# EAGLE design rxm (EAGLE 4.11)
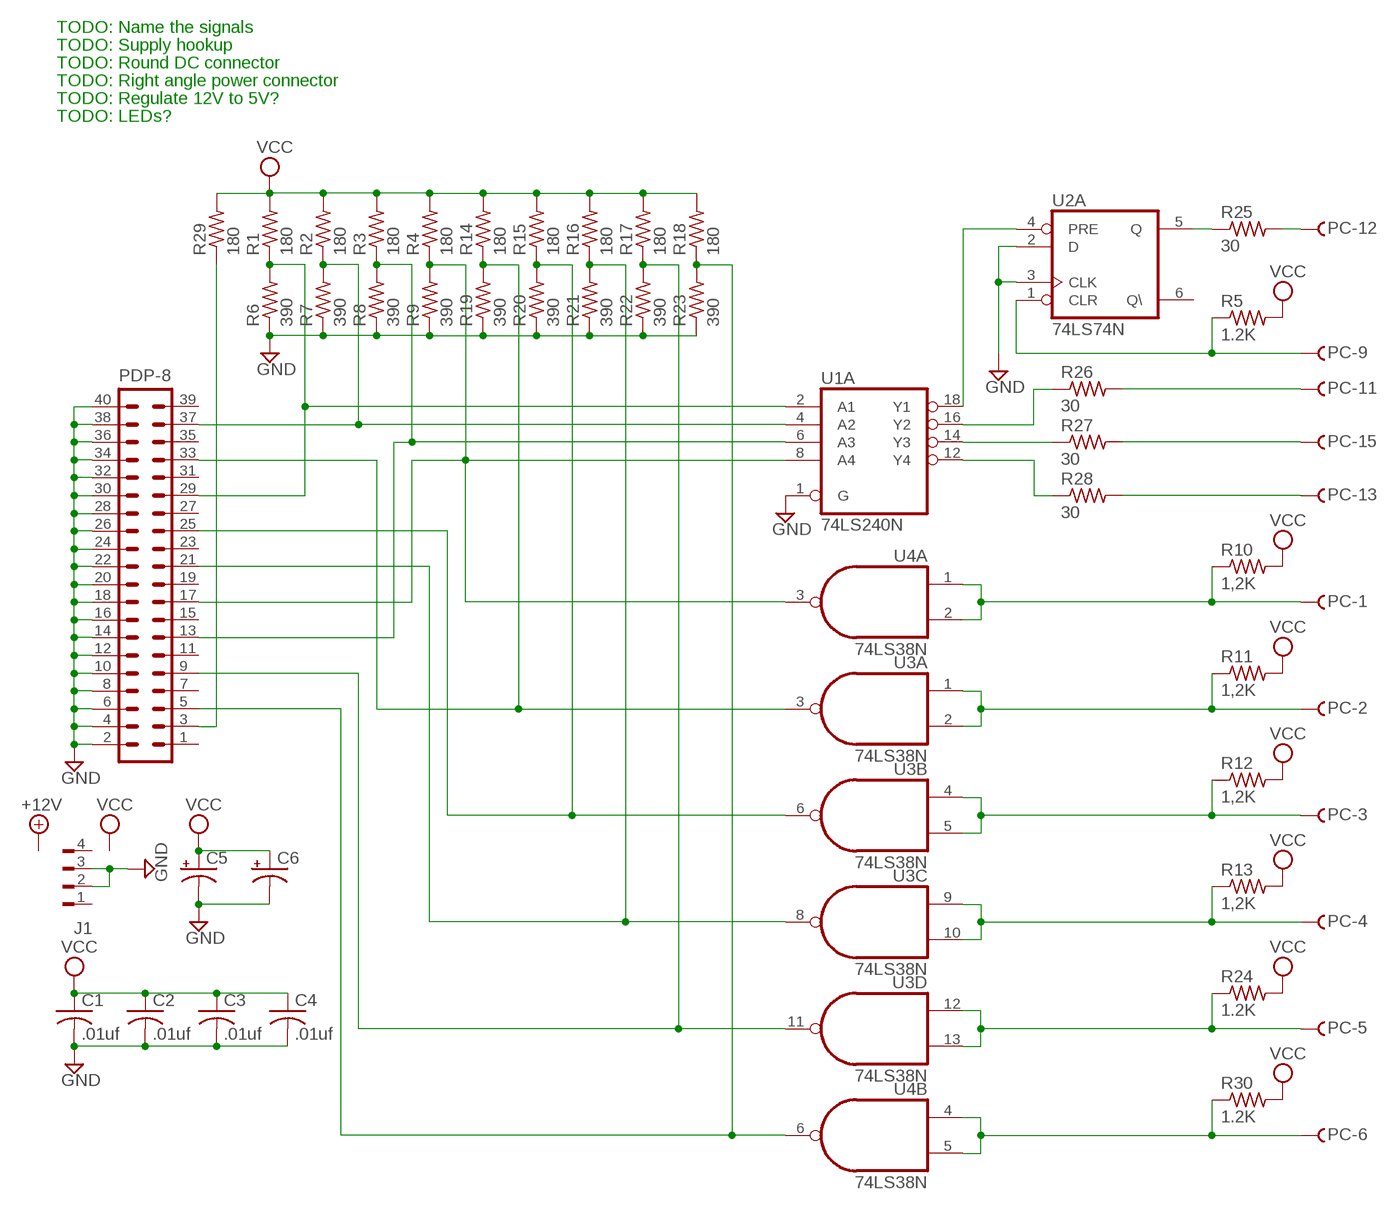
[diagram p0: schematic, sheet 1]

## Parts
C1  .01uf  C-US050-025X075  [C050-025X075]
C2  .01uf  C-US050-025X075  [C050-025X075]
C3  .01uf  C-US050-025X075  [C050-025X075]
C4  .01uf  C-US050-025X075  [C050-025X075]
C5  CPOL-USE2,5-6E  [E2,5-6E]
C6  CPOL-USE2,5-6E  [E2,5-6E]
J1  FLOPPY-4  [FLOPPY-4]
PC  F25HS  [F25H]
PDP-8  40H  [40H]
R1  180  R-US_0207/10  [0207/10]
R2  180  R-US_0207/10  [0207/10]
R3  180  R-US_0207/10  [0207/10]
R4  180  R-US_0207/10  [0207/10]
R5  1.2K  R-US_0207/10  [0207/10]
R6  390  R-US_0207/10  [0207/10]
R7  390  R-US_0207/10  [0207/10]
R8  390  R-US_0207/10  [0207/10]
R9  390  R-US_0207/10  [0207/10]
R10  1,2K  R-US_0207/10  [0207/10]
R11  1,2K  R-US_0207/10  [0207/10]
R12  1,2K  R-US_0207/10  [0207/10]
R13  1,2K  R-US_0207/10  [0207/10]
R14  180  R-US_0207/10  [0207/10]
R15  180  R-US_0207/10  [0207/10]
R16  180  R-US_0207/10  [0207/10]
R17  180  R-US_0207/10  [0207/10]
R18  180  R-US_0207/10  [0207/10]
R19  390  R-US_0207/10  [0207/10]
R20  390  R-US_0207/10  [0207/10]
R21  390  R-US_0207/10  [0207/10]
R22  390  R-US_0207/10  [0207/10]
R23  390  R-US_0207/10  [0207/10]
R24  1.2K  R-US_0207/10  [0207/10]
R25  30  R-US_0207/10  [0207/10]
R26  30  R-US_0207/10  [0207/10]
R27  30  R-US_0207/10  [0207/10]
R28  30  R-US_0207/10  [0207/10]
R29  180  R-US_0207/10  [0207/10]
R30  1.2K  R-US_0207/10  [0207/10]
U1  74LS240N  [DIL20]
U2  74LS74N  [DIL14]
U3  74LS38N  [DIL14]
U4  74LS38N  [DIL14]

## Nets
GND: C1.2 C2.2 C3.2 C4.2 C5.- C6.- J1.2 J1.3 PDP-8.2 PDP-8.4 PDP-8.6 PDP-8.8 PDP-8.10 PDP-8.12 PDP-8.14 PDP-8.16 PDP-8.18 PDP-8.20 PDP-8.22 PDP-8.24 PDP-8.26 PDP-8.28 PDP-8.30 PDP-8.32 PDP-8.34 PDP-8.36 PDP-8.38 PDP-8.40 R6.1 R7.1 R8.1 R9.1 R19.1 R20.1 R21.1 R22.1 R23.1 U1.1(A:G) U2.2(A:D) U2.3(A:CLK)
N$1: PDP-8.29 R1.1 R6.2 U1.2(A:A1)
N$2: PDP-8.37 R2.1 R7.2 U1.4(A:A2)
N$3: PDP-8.13 R3.1 R8.2 U1.6(A:A3)
N$4: PDP-8.17 R4.1 R9.2 U1.8(A:A4) U4.3(A:O)
N$6: PDP-8.33 R14.1 R19.2 U3.3(A:O)
N$7: PDP-8.25 R15.1 R20.2 U3.6(B:O)
N$8: PDP-8.21 R16.1 R21.2 U3.8(C:O)
N$9: PDP-8.9 R17.1 R22.2 U3.11(D:O)
N$10: PDP-8.5 R18.1 R23.2 U4.6(B:O)
N$11: PC.12 R25.2
N$12: PC.11 R26.2
N$13: PC.15 R27.2
N$14: PC.13 R28.2
N$15: PDP-8.3 R29.1
N$16: PC.1 R10.1 U4.1(A:I0) U4.2(A:I1)
N$17: PC.2 R11.1 U3.1(A:I0) U3.2(A:I1)
N$18: PC.3 R12.1 U3.4(B:I0) U3.5(B:I1)
N$19: PC.4 R13.1 U3.9(C:I0) U3.10(C:I1)
N$20: PC.6 R30.1 U4.4(B:I0) U4.5(B:I1)
N$21: PC.5 R24.1 U3.12(D:I0) U3.13(D:I1)
N$22: U1.18(A:Y1) U2.4(A:PRE)
N$23: PC.9 R5.1 U2.1(A:CLR)
N$24: R25.1 U2.5(A:Q)
N$25: R28.1 U1.12(A:Y4)
N$26: R27.1 U1.14(A:Y3)
N$27: R26.1 U1.16(A:Y2)
VCC: C1.1 C2.1 C3.1 C4.1 C5.+ C6.+ R1.2 R2.2 R3.2 R4.2 R5.2 R10.2 R11.2 R12.2 R13.2 R14.2 R15.2 R16.2 R17.2 R18.2 R24.2 R29.2 R30.2
Unconnected: J1.1 J1.4 PC.7 PC.8 PC.10 PC.14 PC.16 PC.17 PC.18 PC.19 PC.20 PC.21 PC.22 PC.23 PC.24 PC.25 PDP-8.1 PDP-8.7 PDP-8.11 PDP-8.15 PDP-8.19 PDP-8.23 PDP-8.27 PDP-8.31 PDP-8.35 PDP-8.39 U1.3(B:Y4) U1.5(B:Y3) U1.7(B:Y2) U1.9(B:Y1) U1.11(B:A1) U1.13(B:A2) U1.15(B:A3) U1.17(B:A4) U1.19(B:G) U2.6(A:Q\) U2.8(B:Q\) U2.9(B:Q) U2.10(B:PRE) U2.11(B:CLK) U2.12(B:D) U2.13(B:CLR) U4.8(C:O) U4.9(C:I0) U4.10(C:I1) U4.11(D:O) U4.12(D:I0) U4.13(D:I1)

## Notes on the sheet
- TODO: Name the signals
- TODO: Supply hookup
- TODO: Round DC connector
- TODO: Right angle power connector
- TODO: Regulate 12V to 5V?
- TODO: LEDs?

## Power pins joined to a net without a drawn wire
GND: U1.10(P:GND) U2.7(P:GND) U3.7(P:GND) U4.7(P:GND)
VCC: U1.20(P:VCC) U2.14(P:VCC) U3.14(P:VCC) U4.14(P:VCC)

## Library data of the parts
C1-C4 = rcl:C-US: CAPACITOR, American symbol
C5 C6 = rcl:CPOL-US: POLARIZED CAPACITOR, American symbol
J1 = con-amp:FLOPPY-4: MATE N-LOCK
PC = con-subd:F25?S: SUB-D
PDP-8 = con-harting-h:40H: CONNECTOR
R1-R30 = rcl:R-US_: RESISTOR, American symbol
U1 = 74xx-jameco:74*240: Octal BUFFER and LINE DRIVER, 3-state
U2 = 74xx-jameco:74*74: Dual D type positive edge triggered FLIP FLOP, preset and clear
U3 U4 = 74xx-jameco:74*38: Quad 2-input NAND gate, open collector output

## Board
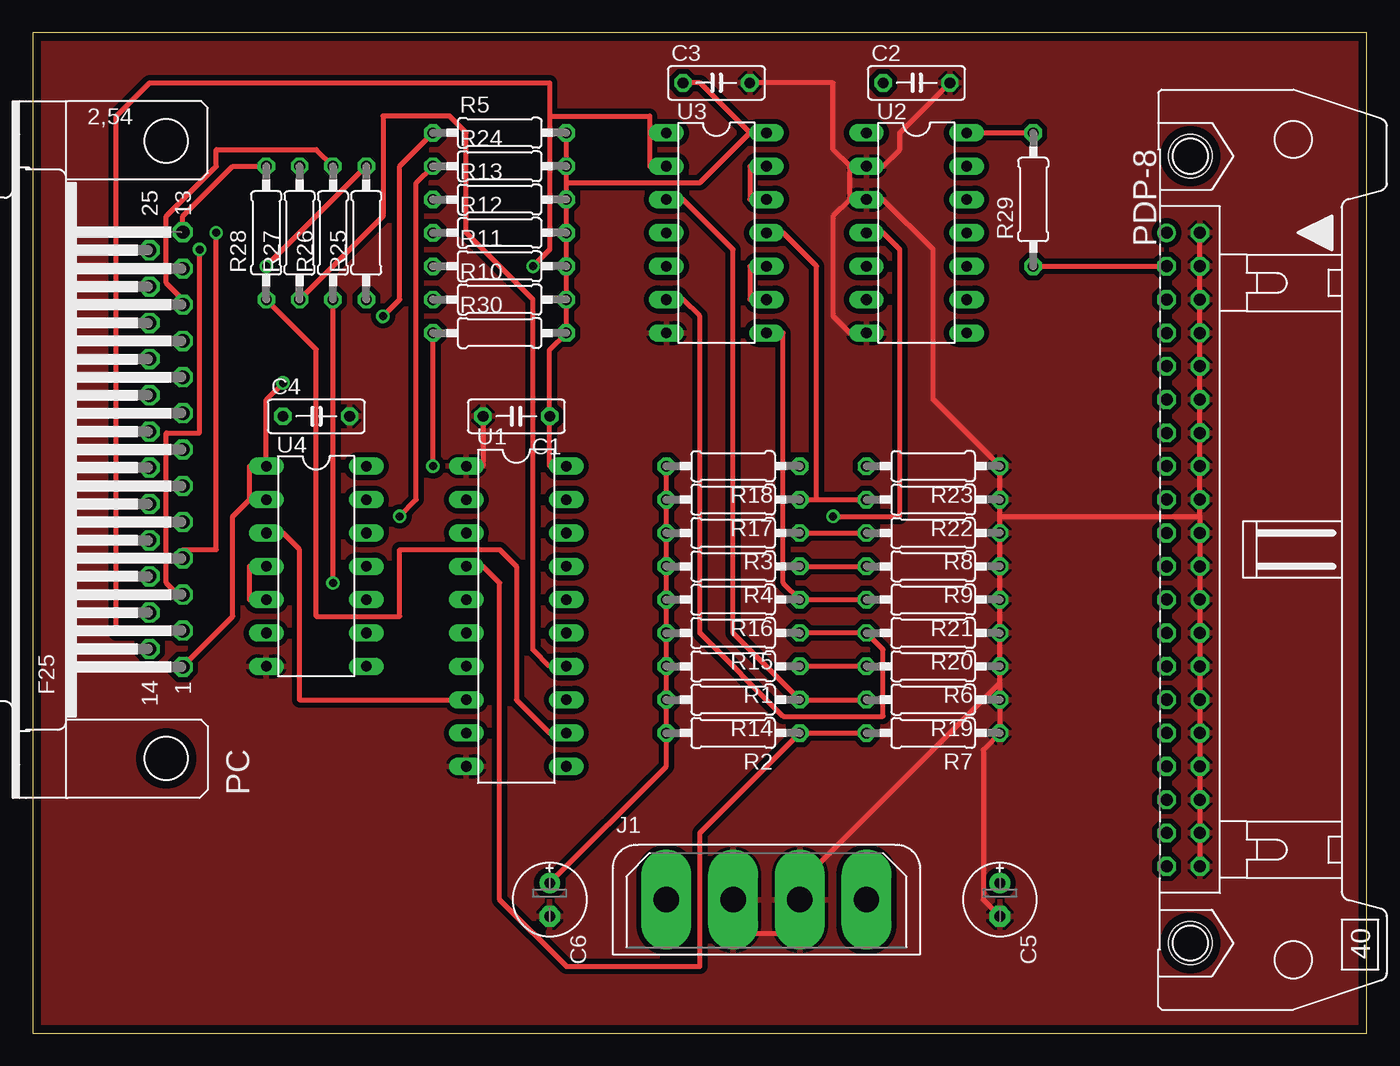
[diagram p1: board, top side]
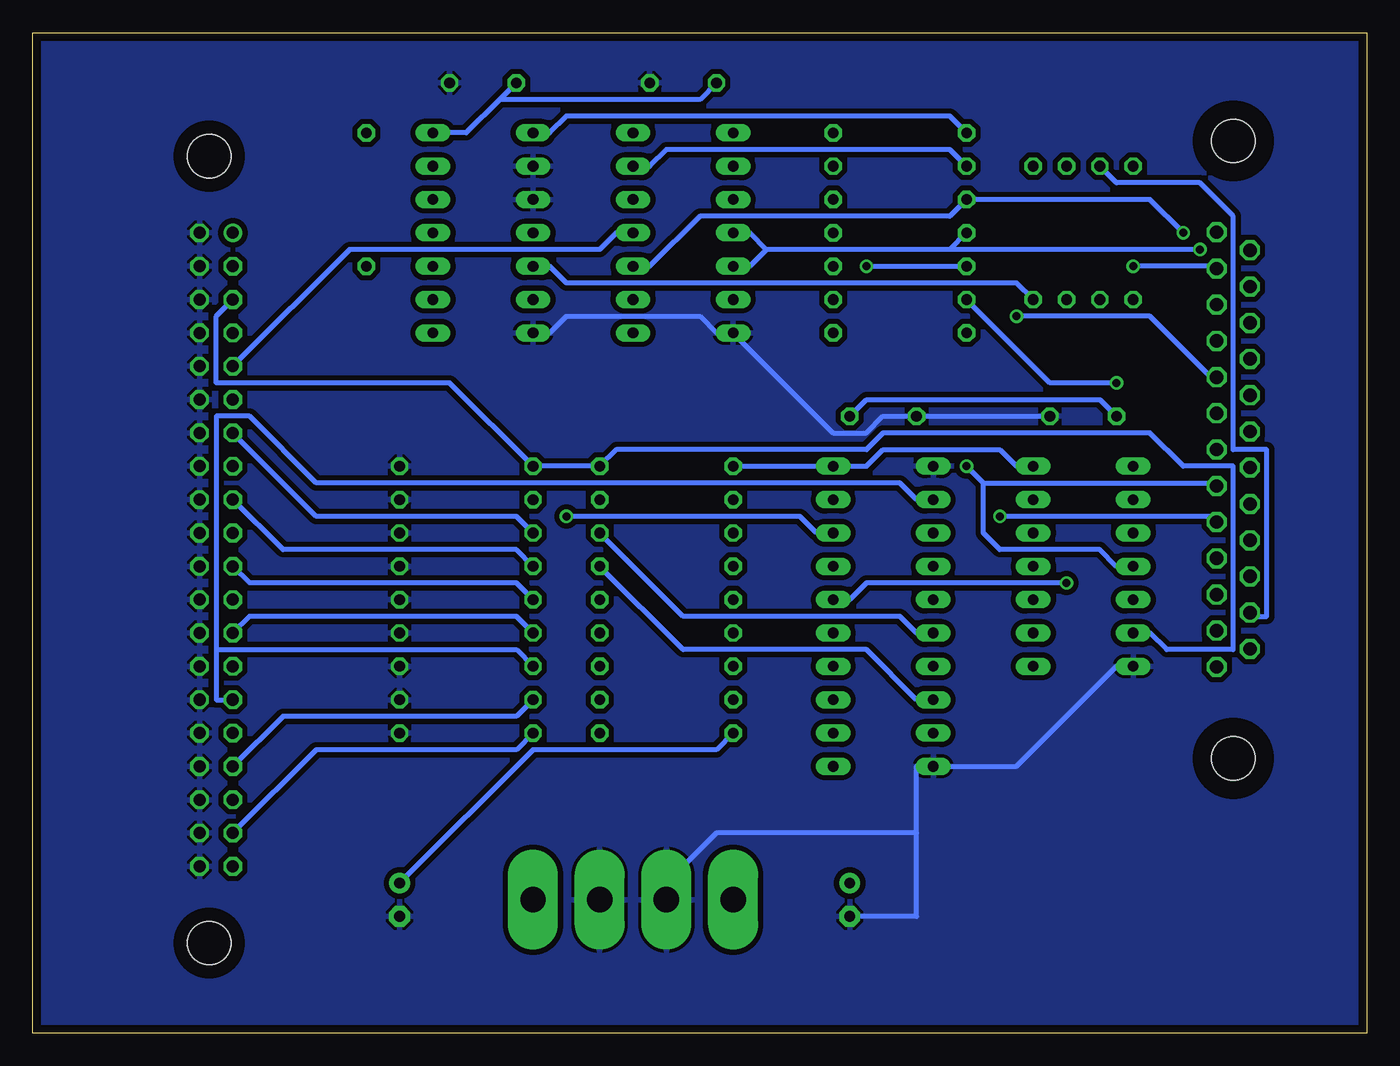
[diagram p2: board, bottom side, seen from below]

Size 101.6 x 76.2 mm. Coordinates in mm from the lower left corner, seen from the top.
Outline: 101.6,76.2 0,76.2 0,0 101.6,0 101.6,76.2
Copper layers (1*16): Top 0.035mm / dielectric 1.5mm / Bottom 0.035mm
Design rules "15mils": minimum track width 15mil, minimum drill 24mil, track to track 15mil, track to pad 10mil, pad to pad 10mil, via to via 10mil, smd to smd 10mil, copper to edge 25mil, drill to drill 10mil, minimum pad ring 10mil, minimum via ring 8mil, stop-mask expansion 0mil, vias tented up to drill 0mil, thermal gap 10mil

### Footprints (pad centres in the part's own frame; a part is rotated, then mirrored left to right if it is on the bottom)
C050-025X075 = drill 0.813 octagon: 1 -2.54,0; 2 2.54,0
E2,5-6E = drill 0.813 pad 1.575 round: + -1.27,0 | drill 0.813 pad 1.575 octagon: - 1.27,0
FLOPPY-4 = drill 1.93 pad 3.81 long: 1 7.62,0; 2 2.54,0; 3 -2.54,0; 4 -7.62,0
F25H = drill 1.016 octagon: 1 -16.561,-1.27; 2 -13.792,-1.27; 3 -11.049,-1.27; 4 -8.28,-1.27; 5 -5.512,-1.27; 6 -2.769,-1.27; 7 0,-1.27; 8 2.769,-1.27; 9 5.512,-1.27; 10 8.28,-1.27; 11 11.049,-1.27; 12 13.792,-1.27; 13 16.561,-1.27; 14 -15.189,1.27; 15 -12.421,1.27; 16 -9.652,1.27; 17 -6.909,1.27; 18 -4.14,1.27; 19 -1.372,1.27; 20 1.372,1.27; 21 4.14,1.27; 22 6.909,1.27; 23 9.652,1.27; 24 12.421,1.27; 25 15.189,1.27 | hole 3.302: -23.52,0; 23.52,0
40H = drill 0.914 round: 1 -24.13,-1.27 | drill 0.914 octagon: 2 -24.13,1.27; 3 -21.59,-1.27; 4 -21.59,1.27; 5 -19.05,-1.27; 6 -19.05,1.27; 7 -16.51,-1.27; 8 -16.51,1.27; 9 -13.97,-1.27; 10 -13.97,1.27; 11 -11.43,-1.27; 12 -11.43,1.27; 13 -8.89,-1.27; 14 -8.89,1.27; 15 -6.35,-1.27; 16 -6.35,1.27; 17 -3.81,-1.27; 18 -3.81,1.27; 19 -1.27,-1.27; 20 -1.27,1.27; 21 1.27,-1.27; 22 1.27,1.27; 23 3.81,-1.27; 24 3.81,1.27; 25 6.35,-1.27; 26 6.35,1.27; 27 8.89,-1.27; 28 8.89,1.27; 29 11.43,-1.27; 30 11.43,1.27; 31 13.97,-1.27; 32 13.97,1.27; 33 16.51,-1.27; 34 16.51,1.27; 35 19.05,-1.27; 36 19.05,1.27; 37 21.59,-1.27; 38 21.59,1.27; 39 24.13,-1.27; 40 24.13,1.27 | hole 3.302: -29.972,0.533; 29.972,0.533
0207/10 = drill 0.813 octagon: 1 -5.08,0; 2 5.08,0
DIL20 = drill 0.813 long: 1 -11.43,-3.81; 2 -8.89,-3.81; 3 -6.35,-3.81; 4 -3.81,-3.81; 5 -1.27,-3.81; 6 1.27,-3.81; 7 3.81,-3.81; 8 6.35,-3.81; 9 8.89,-3.81; 10 11.43,-3.81; 11 11.43,3.81; 12 8.89,3.81; 13 6.35,3.81; 14 3.81,3.81; 15 1.27,3.81; 16 -1.27,3.81; 17 -3.81,3.81; 18 -6.35,3.81; 19 -8.89,3.81; 20 -11.43,3.81
DIL14 = drill 0.813 long: 1 -7.62,-3.81; 2 -5.08,-3.81; 3 -2.54,-3.81; 4 0,-3.81; 5 2.54,-3.81; 6 5.08,-3.81; 7 7.62,-3.81; 8 7.62,3.81; 9 5.08,3.81; 10 2.54,3.81; 11 0,3.81; 12 -2.54,3.81; 13 -5.08,3.81; 14 -7.62,3.81

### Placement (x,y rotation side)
C1  36.83,46.99 180 top
C2  67.31,72.39 0 top
C3  52.07,72.39 0 top
C4  21.59,46.99 0 top
C5  73.66,10.16 270 top
C6  39.37,10.16 270 top
J1  55.88,10.16 0 top
PC  10.16,44.45 90 top
PDP-8  87.63,36.83 270 top
R1  53.34,27.94 180 top
R2  53.34,22.86 180 top
R3  53.34,38.1 180 top
R4  53.34,35.56 180 top
R5  35.56,68.58 0 top
R6  68.58,27.94 180 top
R7  68.58,22.86 180 top
R8  68.58,38.1 180 top
R9  68.58,35.56 180 top
R10  35.56,55.88 0 top
R11  35.56,58.42 0 top
R12  35.56,60.96 0 top
R13  35.56,63.5 0 top
R14  53.34,25.4 180 top
R15  53.34,30.48 180 top
R16  53.34,33.02 180 top
R17  53.34,40.64 180 top
R18  53.34,43.18 180 top
R19  68.58,25.4 180 top
R20  68.58,30.48 180 top
R21  68.58,33.02 180 top
R22  68.58,40.64 180 top
R23  68.58,43.18 180 top
R24  35.56,66.04 0 top
R25  25.4,60.96 90 top
R26  22.86,60.96 90 top
R27  20.32,60.96 90 top
R28  17.78,60.96 90 top
R29  76.2,63.5 90 top
R30  35.56,53.34 0 top
U1  36.83,31.75 270 top
U2  67.31,60.96 270 top
U3  52.07,60.96 270 top
U4  21.59,35.56 270 top

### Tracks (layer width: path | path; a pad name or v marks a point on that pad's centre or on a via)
GND
  Top 0.381: 62.23,63.5 62.23,66.04 | C3.2 60.96,72.39 60.96,67.31 62.23,66.04 | 62.23,66.04 U2.2 64.77,66.04 66.04,67.31 66.04,68.58 C2.2 | C1.2 34.29,43.18 U1.1 | 62.23,63.5 60.96,62.23 60.96,54.61 62.23,53.34 U2.7 | 62.23,63.5 U2.3 64.77,63.5 68.58,59.69 68.58,48.26 R23.1 R22.1 73.66,39.37 | J1.3 54.61,7.62 57.15,7.62 J1.2 59.69,12.7 73.66,26.67 | 73.66,39.37 R8.1 R9.1 R21.1 R20.1 R6.1 73.66,26.67 | C5.- 72.39,10.16 72.39,21.59 R7.1 R19.1 73.66,26.67 | PDP-8.2 PDP-8.4 PDP-8.6 PDP-8.8 PDP-8.10 PDP-8.12 PDP-8.14 PDP-8.16 PDP-8.18 88.9,39.37 | 88.9,39.37 PDP-8.20 PDP-8.22 PDP-8.24 PDP-8.26 PDP-8.28 PDP-8.30 PDP-8.32 PDP-8.34 PDP-8.36 PDP-8.38 PDP-8.40 | 73.66,39.37 88.9,39.37
  Bottom 0.381: C4.2 C1.2 36.83,46.99 38.1,45.72 40.64,45.72 U3.7 49.53,53.34 50.8,54.61 60.96,54.61 62.23,53.34 U2.7 | 34.29,15.24 34.29,8.89 C6.- | 34.29,15.24 34.29,20.32 U1.10 26.67,20.32 19.05,27.94 U4.7 | 34.29,15.24 49.53,15.24 52.07,12.7 J1.3
  pour Bottom (isolate 0.406): 0,0 0,76.2 101.6,76.2 101.6,0
  pour Top (isolate 0.406): 0,0 0,76.2 101.6,76.2 101.6,0
N$1
  Top 0.381: R6.2 R1.1
  Bottom 0.381: 87.63,29.21 87.63,25.4 PDP-8.29 | 87.63,29.21 87.63,46.99 85.09,46.99 80.01,41.91 35.56,41.91 34.29,40.64 U1.2 | R6.2 64.77,29.21 87.63,29.21
N$2
  Top 0.381: R7.2 R2.1 50.8,15.24 50.8,5.08 40.64,5.08 35.56,10.16 35.56,34.29 34.29,35.56 U1.4
  Bottom 0.381: PDP-8.37 80.01,21.59 64.77,21.59 R7.2
N$3
  Top 0.381: R3.1 R8.2
  Bottom 0.381: R3.1 52.07,31.75 35.56,31.75 34.29,30.48 U1.6 | PDP-8.13 80.01,39.37 64.77,39.37 R8.2
N$4
  Top 0.381: U1.8 20.32,25.4 20.32,36.83 19.05,38.1 U4.3 | R4.1 R9.2
  Bottom 0.381: PDP-8.17 82.55,36.83 64.77,36.83 R9.2 | R4.1 52.07,29.21 38.1,29.21 34.29,25.4 U1.8
N$6
  Top 0.381: R19.2 R14.1 53.34,30.48 53.34,59.69 49.53,63.5 U3.3
  Bottom 0.381: PDP-8.33 82.55,24.13 64.77,24.13 R19.2
N$7
  Top 0.381: R15.1 R20.2 64.77,29.21 64.77,24.13 57.15,24.13 50.8,30.48 50.8,54.61 49.53,55.88 U3.6
  Bottom 0.381: PDP-8.25 85.09,31.75 64.77,31.75 R20.2
N$8
  Top 0.381: R21.2 R16.1 57.15,34.29 57.15,53.34 U3.8
  Bottom 0.381: PDP-8.21 85.09,34.29 64.77,34.29 R21.2
N$9
  Top 0.381: 59.69,40.64 R22.2 | R17.1 59.69,40.64 | 59.69,40.64 59.69,58.42 57.15,60.96 U3.11
  Bottom 0.381: PDP-8.9 77.47,59.69 58.42,59.69 57.15,60.96 U3.11
N$10
  Bottom 0.381: U4.6 16.51,30.48 15.24,29.21 10.16,29.21 10.16,43.18 13.97,43.18 16.51,45.72 36.83,45.72 38.1,44.45 57.15,44.45 R18.1 R23.2 69.85,49.53 87.63,49.53 87.63,54.61 PDP-8.5
N$11  (via drill 0.61)
  Top 0.381: v17.78,58.42 R25.2
  Bottom 0.381: v17.78,58.42 11.43,58.42 PC.12
N$12
  Top 0.381: R26.2 21.59,67.31 13.97,67.31 13.97,66.04 10.16,62.23 10.16,57.15 11.43,55.88 PC.11
N$13
  Bottom 0.381: R27.2 19.05,64.77 12.7,64.77 10.16,62.23 10.16,44.45 7.62,44.45 7.62,31.75 8.89,31.75 PC.15
N$14
  Top 0.381: R28.2 15.24,66.04 11.43,62.23 PC.13 11.43,60.96
N$15
  Top 0.381: R29.1 PDP-8.3
N$16  (via drill 0.61)
  Top 0.381: 16.51,40.64 16.51,43.18 U4.1 17.78,48.26 v19.05,49.53 | 16.51,40.64 15.24,39.37 15.24,31.75 11.43,27.94 PC.1 | 16.51,40.64 U4.2
  Bottom 0.381: R10.1 24.13,49.53 v19.05,49.53
N$17  (via drill 0.61)
  Top 0.381: v38.1,58.42 39.37,59.69 39.37,69.85 | 39.37,69.85 46.99,69.85 46.99,68.58 | 46.99,68.58 46.99,66.04 U3.2 | 46.99,68.58 U3.1 | 39.37,69.85 39.37,72.39 8.89,72.39 6.35,69.85 6.35,30.48 11.43,30.48 PC.2
  Bottom 0.381: v38.1,58.42 R11.1
N$18  (via drill 0.61)
  Top 0.381: v12.7,59.69 12.7,45.72 10.16,45.72 10.16,34.29 11.43,33.02 PC.3
  Bottom 0.381: 31.75,59.69 R12.1 | 31.75,59.69 45.72,59.69 | 45.72,59.69 46.99,60.96 U3.4 | 45.72,59.69 46.99,58.42 U3.5 | v12.7,59.69 31.75,59.69
N$19  (via drill 0.61)
  Top 0.381: U3.9 54.61,55.88 54.61,58.42 U3.10 | v13.97,60.96 13.97,36.83 11.43,36.83 PC.4
  Bottom 0.381: U3.10 54.61,58.42 50.8,62.23 31.75,62.23 R13.1 16.51,63.5 v13.97,60.96
N$20  (via drill 0.61)
  Top 0.381: U4.5 16.51,33.02 16.51,35.56 U4.4 | v30.48,43.18 R30.1
  Bottom 0.381: 29.21,41.91 v30.48,43.18 | 29.21,41.91 11.43,41.91 PC.6 | 29.21,41.91 29.21,38.1 27.94,36.83 20.32,36.83 19.05,35.56 U4.4
N$21  (via drill 0.61)
  Top 0.381: U3.12 54.61,63.5 54.61,66.04 U3.13 | v27.94,39.37 29.21,40.64 29.21,64.77 R24.1
  Bottom 0.381: R24.1 31.75,67.31 53.34,67.31 54.61,66.04 U3.13 | v27.94,39.37 11.43,39.37 PC.5
N$22  (via drill 0.61)
  Top 0.381: v60.96,39.37 66.04,39.37 66.04,59.69 64.77,60.96 U2.4
  Bottom 0.381: v60.96,39.37 43.18,39.37 41.91,38.1 U1.18
N$23  (via drill 0.61)
  Top 0.381: v26.67,54.61 27.94,55.88 27.94,66.04 R5.1
  Bottom 0.381: R5.1 31.75,69.85 60.96,69.85 62.23,68.58 U2.1 | v26.67,54.61 16.51,54.61 11.43,49.53 PC.9
N$24
  Bottom 0.381: R25.1 26.67,57.15 60.96,57.15 62.23,58.42 U2.5
N$25
  Top 0.381: R28.1 21.59,52.07 21.59,31.75 27.94,31.75 27.94,36.83 35.56,36.83 36.83,35.56 36.83,25.4 39.37,22.86 U1.12
N$26
  Top 0.381: R27.1 26.67,62.23 26.67,69.85 31.75,69.85 33.02,68.58 33.02,60.96 38.1,55.88 38.1,29.21 39.37,27.94 U1.14
N$27  (via drill 0.61)
  Top 0.381: v22.86,34.29 R26.1
  Bottom 0.381: v22.86,34.29 38.1,34.29 39.37,33.02 U1.16
VCC
  Top 0.381: R18.2 R17.2 R3.2 R4.2 R16.2 R15.2 R1.2 R14.2 R2.2 48.26,20.32 C6.+ | 54.61,68.58 50.8,72.39 C3.1 | U2.14 R29.2 | 40.64,64.77 R24.2 R5.2 | 40.64,64.77 R13.2 R12.2 R11.2 R10.2 R30.2 39.37,52.07 C1.1 39.37,43.18 U1.20 | 54.61,68.58 50.8,64.77 40.64,64.77 | 54.61,68.58 U3.14
  Bottom 0.381: C5.+ 63.5,21.59 49.53,21.59 R2.2 | 66.04,71.12 68.58,68.58 U2.14 | 66.04,71.12 C2.1 | C3.1 50.8,71.12 66.04,71.12 | U4.14 26.67,43.18 27.94,44.45 36.83,44.45 38.1,43.18 U1.20 R18.2 | C4.1 20.32,48.26 38.1,48.26 C1.1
